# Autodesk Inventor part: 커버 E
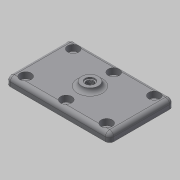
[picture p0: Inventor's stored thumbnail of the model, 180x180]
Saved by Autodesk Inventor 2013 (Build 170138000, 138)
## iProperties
Created: 2020-04
Part Number: 커버 E
Material: 알루미늄 6061
Document SubType Name: Modeling
Designer: mduedu
Density: 1 g/cm^3
Author: mduedu
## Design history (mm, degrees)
sketch "스케치1"
  geometry: L1 (37, 23)-(-37, 23); L2 (-37, 23)-(-37, -23); L3 (-37, -23)-(37, -23); L4 (37, -23)-(37, 23); L5 (37, 23)-(-37, -23); L6 (-37, 23)-(37, -23); 1 further point
  constraints: 12 end point, 2 midpoint, 2 parallel, 1 horizontal, 1 perpendicular
  dimensions: "d0" = 74 distance of L3.end L2.end; "d1" = 46 distance of L2.end L1.end
extrude "돌출1" new body sketch "스케치1" distance "d2" = 6; taper "d3" = 0 deg
sketch "스케치2"
  geometry: C1 r 6 at (0, 0); 1 further point
  constraints: 1 centre point, 1 coincident
  dimensions: "d4" = 12 diameter of C1
extrude "돌출2" join sketch "스케치2" distance "d5" = 3; taper "d6" = 0 deg
fillet "모깎기1" dims "d7" = 3
fillet "모깎기2" dims "d8" = 3
fillet "모깎기3" dims "d9" = 3
sketch "스케치3"
  geometry: L1 (-30, -13)-(30, -13); L2 (30, -13)-(30, 13); L3 (30, 13)-(-30, 13); L4 (-30, 13)-(-30, -13); L5 (-30, -13)-(30, 13); L6 (30, -13)-(-30, 13); 1 further point
  constraints: 12 end point, 2 midpoint, 2 parallel, 1 horizontal, 1 perpendicular
  dimensions: "d10" = 60 distance of L3.end L2.end; "d11" = 26 distance of L2.end L1.end
extrude "돌출3" join sketch "스케치3" distance "d12" = 2; taper "d13" = 0 deg
fillet "모깎기4" dims "d14" = 3
chamfer "모따기1" distance "d15" = 0.5; stored, may be unused: second distance "d16" = 2, angle "d17" = 45 deg
sketch "스케치4"
  geometry: L1 (-29, -17)-(29, -17); L2 (29, -17)-(29, 17); L3 (29, 17)-(-29, 17); L4 (-29, 17)-(-29, -17); L5 (-29, -17)-(29, 17); L6 (29, -17)-(-29, 17); 7 further points
  constraints: 12 end point, 4 coincident, 4 midpoint, 2 parallel, 1 horizontal, 1 perpendicular
  dimensions: "d18" = 58 distance of L3.end L2.end; "d19" = 34 distance of L2.end L1.end
hole "구멍1" sketch "스케치4" at (-29, 17), (-29, -17), (29, -17), (29, 17), (0, 17), (0, -17) diameter "d20" = 4.5; stored, may be unused: countersink angle "d24" = 90 deg, drill point angle "d26" = 118 deg; dims "d21" = 6, "d22" = 8, "d23" = 4.4, "d25" = 8
hole "구멍2" diameter "d29" = 5.188; stored, may be unused: countersink angle "d33" = 90 deg, drill point angle "d35" = 118 deg; dims "d27" = 10, "d28" = 10, "d30" = 6, "d31" = 8, "d32" = 4.4, "d34" = 8
sketch "스케치5"
  geometry: C1 r 3.5 at (0, 0); 1 further point
  constraints: 1 centre point, 1 coincident
  dimensions: "d36" = 7 diameter of C1
extrude "돌출4" cut sketch "스케치5" distance "d37" = 1; taper "d38" = 0 deg
node "솔리드1"
